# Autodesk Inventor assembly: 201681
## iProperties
Created: 2007-10
Part Number: 201681
Document SubType Name: Weldment
Designer: TH
Weld Material: Welded Steel Mild (Black-Flat)
Mass: 742.807 g
Surface Area: 353.059 cm^2
Volume: 94.6232 cm^3
Density: 7.85016 g/cm^3
Description: PIVOT LINK WELDMENT
Component Category: Lower Component
Author: TH
